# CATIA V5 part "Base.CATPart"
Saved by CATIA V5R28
Part number: Base
Material "Light Green": density 7860 kg/m3, Young's modulus 2e+11 Pa, Poisson ratio 0.266
Bounding box of the stored display mesh (mm): x -200 to 200, y -37.5 to 37.5, z -25 to 55
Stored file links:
  C:\Users\Parisa\Desktop\tarah sanat\CAR JACK\Base.CATPart
  C:\Users\Parisa\Desktop\tarah sanat\CAR JACK\Top.CATPart
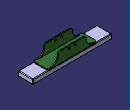
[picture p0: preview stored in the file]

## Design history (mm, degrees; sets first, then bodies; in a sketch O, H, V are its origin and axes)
Body1 (main body)
  Sketch1 on face of Pad4, origin (0, 0, 0), H (1, 0, 0), V (0, -1, 0)
    line L1 (200, 37.5) -> (200, -37.5)
    line L2 (200, -37.5) -> (-200, -37.5)
    line L3 (-200, -37.5) -> (-200, 37.5)
    line L4 (-200, 37.5) -> (200, 37.5)
    length L1 = 75
    length L4 = 400
    vertical: L1 V, L3 V
    horizontal: L2 H, L4 H
    equidistance: L1 L3 O, L2 L4 O
  Pad1: profile Sketch1, direction (0, 0, -1), length 10
  Sketch2 on end face of Pad1, origin (0, 0, -10), H (1, 0, 0), V (0, -1, 0)
  Pad2: profile Sketch2, direction (0, 0, -1), length 15
  AutoFillet1: AutoFilletRadius 3, CurvatureRadius 1.5, RoundRadius 3
Body2, material "Light Green"
  Sketch3 on xy-plane, origin (0, 0, 0), H (1, 0, 0), V (0, 1, 0)
    line L1 (125, 27.5) -> (125, -27.5)
    line L2 (120, -32.5) -> (-120, -32.5)
    line L3 (-125, -27.5) -> (-125, 27.5)
    line L4 (-120, 32.5) -> (120, 32.5)
    arc A1 centre (120, 27.5) radius 5 from (125, 27.5) to (120, 32.5) ccw
    arc A2 centre (120, -27.5) radius 5 from (125, -27.5) to (120, -32.5) cw
    arc A3 centre (-120, -27.5) radius 5 from (-120, -32.5) to (-125, -27.5) cw
    arc A4 centre (-120, 27.5) radius 5 from (-125, 27.5) to (-120, 32.5) cw
    distance L4 L2 = 65
    distance L1 L3 = 250
    radius A1 = 5
    radius A2 = 5
    radius A3 = 5
    radius A4 = 5
    vertical: L1 V, L3 V
    horizontal: L2 H, L4 H
    equidistance: L1 L3 O, L2 L4 O
    tangency: A1 L1, A1 L4, A2 L1, A2 L2, A3 L2, A3 L3, A4 L3, A4 L4
  Pad3: profile Sketch3, direction (0, 0, 1), length 5
  Sketch4 on face of Pad3 from Sketch3.L4, origin (0, 32.5, 0), H (-1, 0, 0), V (0, 0, 1)
    point P1 (-120, 5)
    line L1 (-120, 5) -> (-120, 0)
    point P2 (-120, 0)
    line L2 (-120, 0) -> (120, 0)
    line L3 (120, 0) -> (120, 5)
    point P4 (120, 5)
    line L4 (120, 5) -> (107.9583, 5)
    point P5 (107.9583, 5)
    arc A1 centre (107.9583, 43) radius 38 from (107.9583, 5) to (69.9913, 44.5833) cw
    point P7 (69.9913, 44.5833)
    arc A2 centre (60, 45) radius 10 from (69.9913, 44.5833) to (60, 55) ccw
    point P9 (60, 55)
    line L5 (60, 55) -> (0, 55)
    point P10 (0, 55)
    reference projected line E1 (120, 0) -> (120, 5) from edge [face of Pad3 from Sketch3.A4 | face of Pad3 from Sketch3.L4]
    reference projected line E2 (-120, 5) -> (120, 5) from edge [face of Pad3 from Sketch3.L4 | end face of Pad3]
    reference projected line E3 (-120, 0) -> (-120, 5) from edge [face of Pad3 from Sketch3.L4 | face of Pad3 from Sketch3.A1]
    point P11 (-107.9583, 5)
    point P12 (-120, 5)
    line L6 (-120, 5) -> (-107.9583, 5)
    point P13 (-69.9913, 44.5833)
    arc A3 centre (-107.9583, 43) radius 38 from (-107.9583, 5) to (-69.9913, 44.5833) ccw
    point P15 (-60, 55)
    arc A4 centre (-60, 45) radius 10 from (-69.9913, 44.5833) to (-60, 55) cw
    point P17 (0, 55)
    line L7 (-60, 55) -> (0, 55)
    circle A5 centre (-15, 43) radius 5
    point P18 (-15, 43)
    circle A6 centre (15, 43) radius 5
    radius A2 = 10
    radius A1 = 38
    distance L5 L2 = 55
    length L5 = 60
    radius A5 = 5
    distance P18 V = 15
    distance P18 L7 = 12
    coincidence: P2 H, P10 V, L3 E1, L4 E2, L1 E3, P1 P12, P10 P17
    vertical: L1 V, L3 V
    horizontal: L2 H, L4 H
    tangency: A1 L4, A2 A1, L5 A2, L6 A3
    symmetry: P5 P11 V, P4 P12 V, L4 L6 V, P7 P13 V, A1 A3 V, P9 P15 V, A2 A4 V, P10 P17 V, L5 L7 V, A5 A6 V
  Pad4: profile Sketch4, direction (0, 1, 0), length 5
  Mirror1: of Pad4, about zx-plane
  Sketch5 on face of Pad4, origin (0, 0, 5), H (1, 0, 0), V (0, 1, 0)
    line L1 (50, 20) -> (50, -20)
    line L2 (50, -20) -> (-50, -20)
    line L3 (-50, -20) -> (-50, 20)
    line L4 (-50, 20) -> (50, 20)
    length L1 = 40
    length L4 = 100
    vertical: L1 V, L3 V
    horizontal: L2 H, L4 H
    equidistance: L1 L3 O, L2 L4 O
  Pocket1: profile Sketch5, direction (0, 0, -1), length 2
  AutoFillet2: AutoFilletRadius 1, CurvatureRadius 1, RoundRadius 1
Current feature: Mirror1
